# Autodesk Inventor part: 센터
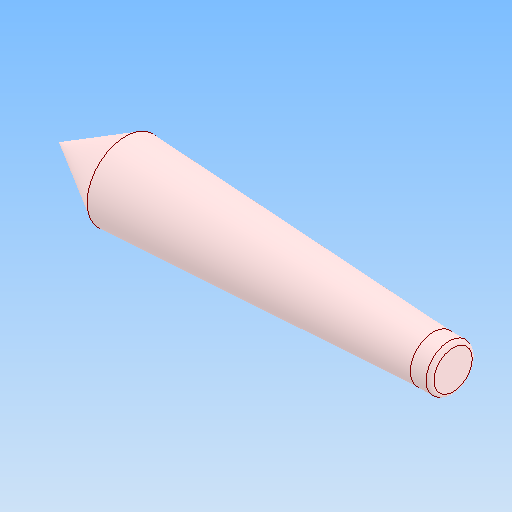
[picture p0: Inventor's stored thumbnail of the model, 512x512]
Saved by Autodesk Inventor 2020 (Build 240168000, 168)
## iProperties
Created: 2024-07
Part Number: 센터
Material: 강철, 합금
Document SubType Name: Modeling
Designer: oem
Density: 7.73 g/cm^3
Appearance: 기본값
Author: jhkim
Sending System: Autodesk Inventor 2025
Preprocessor: ST-DEVELOPER v20
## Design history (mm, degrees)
feature "솔리드1"
node "솔리드2"
